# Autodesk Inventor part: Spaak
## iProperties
Created: 2007-06
Part Number: Spaak
Material: Steel
Document SubType Name: Modeling
Designer: Phil Trethewie
Author: Phil Trethewie
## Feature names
1. Extrusion1
